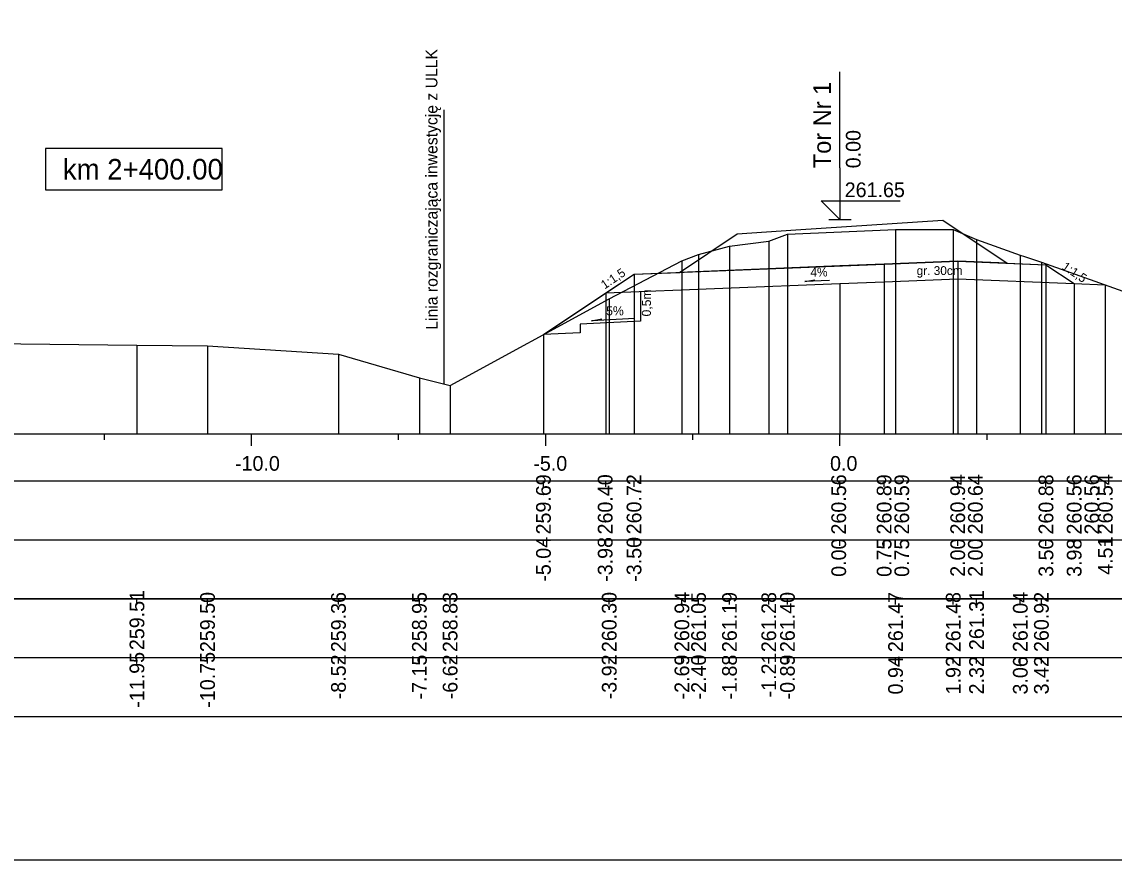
# Model space of a CAD drawing. Extents: x 6516023 to 6560129, y 5513077 to 5529206.
# Drawn here: x 6517241.36 to 6517259.92, y 5513364.27 to 5513378.52 of the extents above; entities that cross this region are included whole.
import ezdxf

# ---------------------------------------------------------------- set-up
doc = ezdxf.new("R2010")
doc.units = 0
for name, color, linetype in [('IR_default', 7, 'Continuous'), ('TOR_PRZEK_P-komponent', 7, 'Continuous'), ('TOR_PRZEK_P-opisy', 7, 'Continuous'), ('TOR_PRZEK_P-schodkowanie+wymiana', 7, 'Continuous'), ('TOR_PRZEK_P-tabelka istniejace', 7, 'Continuous'), ('TOR_PRZEK_P-tabelka projektowane', 7, 'Continuous'), ('TOR_PRZEK_P-teren istniejacy', 7, 'Continuous'), ('TOR_PRZEK_P-tory projektowane', 7, 'Continuous'), ('TOR_PRZEK_P-uklad odniesienia', 7, 'Continuous'), ('TOR_PRZEK_P-warstwa ochronna I', 7, 'Continuous'), ('TOR_PRZEK_P-warstwa ochronna II', 7, 'Continuous'), ('TOR_PS_T-granica PKP-projektowana', 7, 'Continuous'), ('TOR_PS_T-skarpy projektowane', 7, 'Continuous'), ('TOR_RAMKI-ramka+tabelka 1', 7, 'Continuous')]:
    doc.layers.add(name, color=color, linetype=linetype)

msp = doc.modelspace()

# ---------------------------------------------------------------- linework, layer by layer
at = {"layer": 'IR_default'}
msp.add_lwpolyline([(6517250.224, 5513373.201), (6517251.285, 5513373.908), (6517251.763, 5513374.227), (6517252.534, 5513374.258), (6517253.516, 5513374.912), (6517254.513, 5513374.979), (6517257.008, 5513375.145), (6517258.106, 5513374.413), (6517258.763, 5513374.387), (6517258.763, 5513374.387), (6517259.242, 5513374.068)], dxfattribs=at)
at = {"layer": 'TOR_PRZEK_P-komponent'}
msp.add_lwpolyline([(6517253.516, 5513374.912), (6517254.513, 5513374.979), (6517257.008, 5513375.145), (6517258.106, 5513374.413), (6517257.263, 5513374.447), (6517256.013, 5513374.397), (6517255.263, 5513374.367), (6517252.534, 5513374.258)], close=True, dxfattribs=at)
at = {"layer": 'TOR_PRZEK_P-opisy'}
msp.add_lwpolyline([(6517255.084, 5513374.122), (6517254.666, 5513374.102), (6517254.834, 5513374.131)], dxfattribs=at)
at = {"layer": 'TOR_PRZEK_P-schodkowanie+wymiana'}
for p, q in [((6517251.871, 5513373.931), (6517251.871, 5513373.431)), ((6517251.871, 5513373.431), (6517250.848, 5513373.38)), ((6517250.848, 5513373.232), (6517250.224, 5513373.201)), ((6517250.848, 5513373.38), (6517250.848, 5513373.232))]:
    msp.add_line(p, q, dxfattribs=at)
at = {"layer": 'TOR_PRZEK_P-tabelka istniejace'}
for p, q in [((6517243.317, 5513368.611), (6517243.317, 5513368.711)), ((6517244.516, 5513368.611), (6517244.516, 5513368.711)), ((6517246.741, 5513368.611), (6517246.741, 5513368.711)), ((6517248.116, 5513368.611), (6517248.116, 5513368.711)), ((6517248.638, 5513368.611), (6517248.638, 5513368.711)), ((6517251.342, 5513368.611), (6517251.342, 5513368.711)), ((6517252.577, 5513368.611), (6517252.577, 5513368.711)), ((6517252.86, 5513368.611), (6517252.86, 5513368.711)), ((6517253.385, 5513368.611), (6517253.385, 5513368.711)), ((6517254.053, 5513368.611), (6517254.053, 5513368.711)), ((6517254.37, 5513368.611), (6517254.37, 5513368.711)), ((6517256.207, 5513368.611), (6517256.207, 5513368.711)), ((6517257.187, 5513368.611), (6517257.187, 5513368.711)), ((6517257.583, 5513368.611), (6517257.583, 5513368.711)), ((6517258.327, 5513368.611), (6517258.327, 5513368.711)), ((6517258.685, 5513368.611), (6517258.685, 5513368.711)), ((6517226.463, 5513367.711), (6517280.263, 5513367.711)), ((6517243.317, 5513367.611), (6517243.317, 5513367.711)), ((6517244.516, 5513367.611), (6517244.516, 5513367.711)), ((6517246.741, 5513367.611), (6517246.741, 5513367.711)), ((6517248.116, 5513367.611), (6517248.116, 5513367.711)), ((6517248.638, 5513367.611), (6517248.638, 5513367.711)), ((6517251.342, 5513367.611), (6517251.342, 5513367.711)), ((6517252.577, 5513367.611), (6517252.577, 5513367.711)), ((6517252.86, 5513367.611), (6517252.86, 5513367.711)), ((6517253.385, 5513367.611), (6517253.385, 5513367.711)), ((6517254.053, 5513367.611), (6517254.053, 5513367.711)), ((6517254.37, 5513367.611), (6517254.37, 5513367.711)), ((6517256.207, 5513367.611), (6517256.207, 5513367.711)), ((6517257.187, 5513367.611), (6517257.187, 5513367.711)), ((6517257.583, 5513367.611), (6517257.583, 5513367.711)), ((6517258.327, 5513367.611), (6517258.327, 5513367.711)), ((6517258.685, 5513367.611), (6517258.685, 5513367.711))]:
    msp.add_line(p, q, dxfattribs=at)
for points in [[(6517254.37, 5513374.91), (6517254.37, 5513371.711), (6517254.37, 5513371.581), (6517254.37, 5513371.511)], [(6517256.207, 5513374.986), (6517256.207, 5513371.711), (6517256.207, 5513371.581), (6517256.207, 5513371.511)], [(6517257.187, 5513374.986), (6517257.187, 5513371.711), (6517257.187, 5513371.581), (6517257.187, 5513371.511)], [(6517253.385, 5513374.701), (6517253.385, 5513371.711), (6517253.385, 5513371.581), (6517253.385, 5513371.511)], [(6517254.053, 5513374.788), (6517254.053, 5513371.711), (6517254.053, 5513371.581), (6517254.053, 5513371.511)], [(6517257.583, 5513374.819), (6517257.583, 5513371.711), (6517257.583, 5513371.581), (6517257.583, 5513371.511)], [(6517252.86, 5513374.559), (6517252.86, 5513371.711), (6517252.86, 5513371.581), (6517252.86, 5513371.511)], [(6517258.327, 5513374.551), (6517258.327, 5513371.711), (6517258.327, 5513371.581), (6517258.327, 5513371.511)], [(6517252.577, 5513374.456), (6517252.577, 5513371.711), (6517252.577, 5513371.581), (6517252.577, 5513371.511)], [(6517258.685, 5513374.434), (6517258.685, 5513371.711), (6517258.685, 5513371.581), (6517258.685, 5513371.511)], [(6517251.342, 5513373.81), (6517251.342, 5513371.711), (6517251.342, 5513371.581), (6517251.342, 5513371.511)], [(6517243.317, 5513373.019), (6517243.317, 5513371.711), (6517243.317, 5513371.581), (6517243.317, 5513371.511)], [(6517244.516, 5513373.008), (6517244.516, 5513371.711), (6517244.516, 5513371.581), (6517244.516, 5513371.511)], [(6517246.741, 5513372.869), (6517246.741, 5513371.711), (6517246.741, 5513371.581), (6517246.741, 5513371.511)], [(6517248.116, 5513372.465), (6517248.116, 5513371.711), (6517248.116, 5513371.581), (6517248.116, 5513371.511)], [(6517248.638, 5513372.336), (6517248.638, 5513371.711), (6517248.638, 5513371.581), (6517248.638, 5513371.511)]]:
    msp.add_lwpolyline(points, dxfattribs=at)
msp.add_lwpolyline([(6517226.463, 5513368.711), (6517226.463, 5513366.711), (6517280.263, 5513366.711), (6517280.263, 5513368.711)], close=True, dxfattribs=at)
at = {"layer": 'TOR_PRZEK_P-tabelka projektowane'}
for p, q in [((6517250.224, 5513370.611), (6517250.224, 5513370.711)), ((6517251.285, 5513370.611), (6517251.285, 5513370.711)), ((6517251.763, 5513370.611), (6517251.763, 5513370.711)), ((6517255.263, 5513370.611), (6517255.263, 5513370.711)), ((6517256.013, 5513370.611), (6517256.013, 5513370.711)), ((6517256.013, 5513370.611), (6517256.013, 5513370.711)), ((6517257.263, 5513370.611), (6517257.263, 5513370.711)), ((6517257.263, 5513370.611), (6517257.263, 5513370.711)), ((6517258.763, 5513370.611), (6517258.763, 5513370.711)), ((6517259.242, 5513370.611), (6517259.242, 5513370.711)), ((6517259.242, 5513370.611), (6517259.242, 5513370.711)), ((6517259.771, 5513370.611), (6517259.771, 5513370.711)), ((6517226.463, 5513369.711), (6517280.263, 5513369.711)), ((6517250.224, 5513369.611), (6517250.224, 5513369.711)), ((6517251.285, 5513369.611), (6517251.285, 5513369.711)), ((6517251.763, 5513369.611), (6517251.763, 5513369.711)), ((6517255.263, 5513369.611), (6517255.263, 5513369.711)), ((6517256.013, 5513369.611), (6517256.013, 5513369.711)), ((6517256.013, 5513369.611), (6517256.013, 5513369.711)), ((6517257.263, 5513369.611), (6517257.263, 5513369.711)), ((6517257.263, 5513369.611), (6517257.263, 5513369.711)), ((6517258.763, 5513369.611), (6517258.763, 5513369.711)), ((6517259.242, 5513369.611), (6517259.242, 5513369.711)), ((6517259.242, 5513369.611), (6517259.242, 5513369.711)), ((6517259.771, 5513369.611), (6517259.771, 5513369.711))]:
    msp.add_line(p, q, dxfattribs=at)
for points in [[(6517256.013, 5513374.397), (6517256.013, 5513371.711), (6517256.013, 5513371.581), (6517256.013, 5513371.511)], [(6517257.263, 5513374.447), (6517257.263, 5513371.711), (6517257.263, 5513371.581), (6517257.263, 5513371.511)], [(6517258.763, 5513374.387), (6517258.763, 5513371.711), (6517258.763, 5513371.581), (6517258.763, 5513371.511)], [(6517251.763, 5513374.227), (6517251.763, 5513371.711), (6517251.763, 5513371.581), (6517251.763, 5513371.511)], [(6517257.263, 5513374.147), (6517257.263, 5513371.711), (6517257.263, 5513371.581), (6517257.263, 5513371.511)], [(6517255.263, 5513374.067), (6517255.263, 5513371.711), (6517255.263, 5513371.581), (6517255.263, 5513371.511)], [(6517256.013, 5513374.097), (6517256.013, 5513371.711), (6517256.013, 5513371.581), (6517256.013, 5513371.511)], [(6517259.242, 5513374.068), (6517259.242, 5513371.711), (6517259.242, 5513371.581), (6517259.242, 5513371.511)], [(6517259.242, 5513374.068), (6517259.242, 5513371.711), (6517259.242, 5513371.581), (6517259.242, 5513371.511)], [(6517259.771, 5513374.047), (6517259.771, 5513371.711), (6517259.771, 5513371.581), (6517259.771, 5513371.511)], [(6517251.285, 5513373.908), (6517251.285, 5513371.711), (6517251.285, 5513371.581), (6517251.285, 5513371.511)], [(6517250.224, 5513373.201), (6517250.224, 5513371.711), (6517250.224, 5513371.581), (6517250.224, 5513371.511)]]:
    msp.add_lwpolyline(points, dxfattribs=at)
msp.add_lwpolyline([(6517226.463, 5513370.711), (6517226.463, 5513368.711), (6517280.263, 5513368.711), (6517280.263, 5513370.711)], close=True, dxfattribs=at)
at = {"layer": 'TOR_PRZEK_P-teren istniejacy'}
msp.add_lwpolyline([(6517230.263, 5513373), (6517233.229, 5513373.023), (6517237.381, 5513373.071), (6517240.845, 5513373.047), (6517243.317, 5513373.019), (6517244.516, 5513373.008), (6517246.741, 5513372.869), (6517248.116, 5513372.465), (6517248.638, 5513372.336), (6517251.342, 5513373.81), (6517252.577, 5513374.456), (6517252.86, 5513374.559), (6517253.385, 5513374.701), (6517254.053, 5513374.788), (6517254.37, 5513374.91), (6517256.207, 5513374.986), (6517257.187, 5513374.986), (6517257.583, 5513374.819), (6517258.327, 5513374.551), (6517258.399, 5513374.527), (6517258.685, 5513374.434), (6517260.323, 5513373.849)], dxfattribs=at)
at = {"layer": 'TOR_PRZEK_P-tory projektowane'}
for p, q in [((6517255.263, 5513376.034), (6517255.263, 5513377.667)), ((6517255.263, 5513376.034), (6517255.263, 5513375.157)), ((6517255.263, 5513375.157), (6517254.944, 5513375.476)), ((6517254.944, 5513375.476), (6517256.288, 5513375.476)), ((6517255.072, 5513375.157), (6517255.455, 5513375.157))]:
    msp.add_line(p, q, dxfattribs=at)
at = {"layer": 'TOR_PRZEK_P-uklad odniesienia'}
for p, q in [((6517230.263, 5513371.511), (6517280.263, 5513371.511)), ((6517242.763, 5513371.411), (6517242.763, 5513371.511)), ((6517245.263, 5513371.311), (6517245.263, 5513371.511)), ((6517247.763, 5513371.411), (6517247.763, 5513371.511)), ((6517250.263, 5513371.311), (6517250.263, 5513371.511)), ((6517252.763, 5513371.411), (6517252.763, 5513371.511)), ((6517255.263, 5513371.311), (6517255.263, 5513371.511)), ((6517257.763, 5513371.411), (6517257.763, 5513371.511))]:
    msp.add_line(p, q, dxfattribs=at)
msp.add_lwpolyline([(6517244.763, 5513376.361), (6517241.763, 5513376.361), (6517241.763, 5513375.661), (6517244.763, 5513375.661)], close=True, dxfattribs=at)
at = {"layer": 'TOR_PRZEK_P-warstwa ochronna I'}
msp.add_lwpolyline([(6517251.285, 5513373.908), (6517255.263, 5513374.067), (6517256.013, 5513374.097), (6517257.263, 5513374.147), (6517259.242, 5513374.068)], dxfattribs=at)
at = {"layer": 'TOR_PRZEK_P-warstwa ochronna II'}
msp.add_lwpolyline([(6517250.224, 5513373.201), (6517251.763, 5513374.227), (6517256.013, 5513374.397), (6517257.263, 5513374.447), (6517258.763, 5513374.387), (6517259.242, 5513374.068), (6517259.771, 5513374.047)], dxfattribs=at)
at = {"layer": 'TOR_PS_T-granica PKP-projektowana'}
msp.add_line((6517248.536, 5513372.362), (6517248.536, 5513377.019), dxfattribs=at)
at = {"layer": 'TOR_PS_T-skarpy projektowane'}
msp.add_lwpolyline([(6517251.778, 5513373.476), (6517251.043, 5513373.436), (6517251.216, 5513373.467)], dxfattribs=at)
at = {"layer": 'TOR_RAMKI-ramka+tabelka 1'}
msp.add_lwpolyline([(6517109.813, 5513392.767), (6517357.313, 5513392.767), (6517357.313, 5513364.267), (6517109.813, 5513364.267)], close=True, dxfattribs=at)

# ---------------------------------------------------------------- texts
at = {"layer": 'TOR_PRZEK_P-opisy'}
for s, rotation, p in [('1:1,5', 34.0701, (6517251.264, 5513373.966)), ('4%', 0.1515, (6517254.761, 5513374.187)), ('1:1,5', 325.9299, (6517259.022, 5513374.324))]:
    msp.add_text(s, height=0.15, rotation=rotation, dxfattribs=at).set_placement(p)
at = {"layer": 'TOR_PRZEK_P-schodkowanie+wymiana'}
msp.add_text('0,5m', height=0.1545, rotation=90, dxfattribs=at).set_placement((6517252.051, 5513373.509))
at = {"layer": 'TOR_PRZEK_P-tabelka istniejace'}
for s, p in [('259.51', (6517243.442, 5513367.837)), ('259.50', (6517244.641, 5513367.803)), ('259.36', (6517246.866, 5513367.802)), ('258.95', (6517248.241, 5513367.802)), ('258.83', (6517248.763, 5513367.803)), ('260.30', (6517251.467, 5513367.803)), ('260.94', (6517252.702, 5513367.804)), ('261.05', (6517252.985, 5513367.802)), ('261.19', (6517253.51, 5513367.803)), ('261.28', (6517254.178, 5513367.802)), ('261.40', (6517254.495, 5513367.803)), ('261.47', (6517256.332, 5513367.803)), ('261.48', (6517257.312, 5513367.802)), ('261.31', (6517257.708, 5513367.837)), ('261.04', (6517258.452, 5513367.804)), ('260.92', (6517258.81, 5513367.805)), ('-11.95', (6517243.442, 5513366.858)), ('-10.75', (6517244.641, 5513366.858)), ('-8.52', (6517246.866, 5513367.001)), ('-7.15', (6517248.241, 5513366.998)), ('-6.62', (6517248.763, 5513367.001)), ('-3.92', (6517251.467, 5513367.001)), ('-2.69', (6517252.702, 5513366.999)), ('-2.40', (6517252.985, 5513366.999)), ('-1.88', (6517253.51, 5513366.998)), ('-1.21', (6517254.178, 5513367.033)), ('-0.89', (6517254.495, 5513366.999)), ('0.94', (6517256.332, 5513367.083)), ('1.92', (6517257.312, 5513367.084)), ('2.32', (6517257.708, 5513367.084)), ('3.06', (6517258.452, 5513367.082)), ('3.42', (6517258.81, 5513367.084))]:
    msp.add_text(s, height=0.25, rotation=90, dxfattribs=at).set_placement(p)
at = {"layer": 'TOR_PRZEK_P-tabelka projektowane'}
for s, p in [('259.69', (6517250.349, 5513369.803)), ('260.40', (6517251.398, 5513369.803)), ('260.72', (6517251.888, 5513369.805)), ('260.56', (6517255.366, 5513369.802)), ('260.89', (6517256.138, 5513369.803)), ('260.59', (6517256.438, 5513369.803)), ('260.94', (6517257.388, 5513369.804)), ('260.64', (6517257.688, 5513369.804)), ('260.88', (6517258.888, 5513369.802)), ('260.56', (6517259.367, 5513369.802)), ('260.56', (6517259.667, 5513369.802)), ('260.54', (6517259.896, 5513369.804)), ('-5.04', (6517250.349, 5513369)), ('-3.98', (6517251.398, 5513368.998)), ('-3.50', (6517251.888, 5513368.999)), ('0.00', (6517255.366, 5513369.083)), ('0.75', (6517256.138, 5513369.082)), ('0.75', (6517256.438, 5513369.082)), ('2.00', (6517257.388, 5513369.083)), ('2.00', (6517257.688, 5513369.083)), ('3.50', (6517258.888, 5513369.083)), ('3.98', (6517259.367, 5513369.082)), ('4.51', (6517259.896, 5513369.117))]:
    msp.add_text(s, height=0.25, rotation=90, dxfattribs=at).set_placement(p)
at = {"layer": 'TOR_PRZEK_P-tory projektowane'}
for s, height, p in [('Tor Nr 1', 0.3, (6517255.109, 5513376.028)), ('0.00', 0.25, (6517255.613, 5513376.027))]:
    msp.add_text(s, height=height, rotation=90, dxfattribs=at).set_placement(p)
msp.add_text('261.65', height=0.25, dxfattribs=at).set_placement((6517255.343, 5513375.537))
at = {"layer": 'TOR_PRZEK_P-uklad odniesienia'}
for s, height, p in [('km 2+400.00', 0.35, (6517242.058, 5513375.836)), ('-10.0', 0.25, (6517244.983, 5513370.886)), ('-5.0', 0.25, (6517250.052, 5513370.886)), ('0.0', 0.25, (6517255.094, 5513370.886))]:
    msp.add_text(s, height=height, dxfattribs=at).set_placement(p)
at = {"layer": 'TOR_PRZEK_P-warstwa ochronna I'}
msp.add_text('gr. 30cm', height=0.15, dxfattribs=at).set_placement((6517256.566, 5513374.213))
at = {"layer": 'TOR_PS_T-granica PKP-projektowana'}
msp.add_text('Linia rozgraniczająca inwestycję z ULLK', height=0.2, rotation=90.0511, dxfattribs=at).set_placement((6517248.426, 5513373.283))
at = {"layer": 'TOR_PS_T-skarpy projektowane'}
msp.add_text('5%', height=0.1545, dxfattribs=at).set_placement((6517251.29, 5513373.527))

doc.saveas('drawing.dxf')
